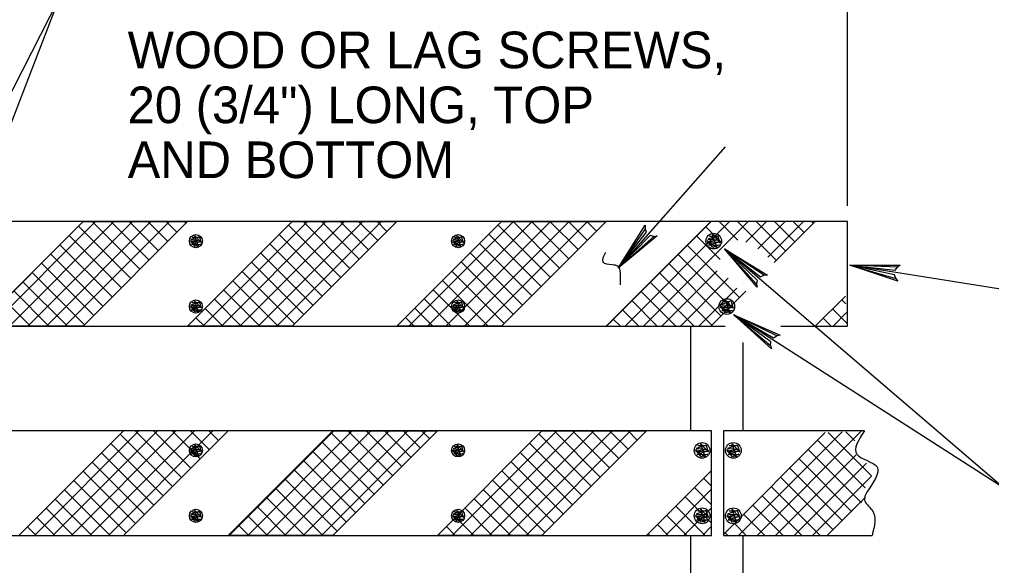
# Model space of a CAD drawing. Extents: x -4 to 901, y -468 to 720.
# Drawn here: x 180 to 269.2, y -1.4 to 48.7 of the extents above; entities that cross this region are included whole.
import ezdxf

# ---------------------------------------------------------------- set-up
doc = ezdxf.new("R2010")
doc.units = 0
doc.layers.add('2', color=7, linetype='Continuous')
doc.layers.add('3', color=7, linetype='Continuous')

msp = doc.modelspace()

# ---------------------------------------------------------------- linework, layer by layer
at = {"layer": '2'}
for p, q in [((255.99775, 41.059875), (255.99775, 66.373875)), ((255.99775, 31.603875), (255.99775, 41.059875)), ((176.23175, 20.563875), (185.83175, 30.163875)), ((185.83175, 20.563875), (195.43175, 30.163875)), ((195.43175, 20.563875), (205.03175, 30.163875)), ((205.03175, 20.563875), (214.63175, 30.163875)), ((214.63175, 20.563875), (224.23175, 30.163875)), ((224.23175, 20.563875), (233.83175, 30.163875)), ((233.83175, 20.563875), (243.43175, 30.163875)), ((249.2665, 26.398625), (253.03175, 30.163875)), ((196.41975, 28.735875), (195.72975, 28.501875)), ((195.85575, 28.735875), (196.41975, 28.735875)), ((196.43175, 27.877875), (196.08975, 28.861875)), ((196.08975, 28.861875), (196.68975, 28.219875)), ((196.68975, 28.219875), (196.50975, 28.801875)), ((220.48375, 28.735875), (219.79375, 28.501875)), ((219.91975, 28.735875), (220.48375, 28.735875)), ((220.49575, 27.877875), (220.15375, 28.861875)), ((220.15375, 28.861875), (220.75375, 28.219875)), ((220.75375, 28.219875), (220.57375, 28.801875)), ((243.99175, 28.809875), (243.16375, 28.527875)), ((243.31575, 28.809875), (243.99175, 28.809875)), ((244.00575, 27.779875), (243.59575, 28.959875)), ((243.59575, 28.959875), (244.31575, 28.189875)), ((244.31575, 28.189875), (244.09975, 28.887875)), ((196.57575, 28.453875), (195.68775, 28.285875)), ((196.11375, 27.877875), (195.68775, 28.423875)), ((195.68775, 28.423875), (196.43175, 27.877875)), ((195.68775, 28.285875), (196.67775, 28.321875)), ((195.72975, 28.501875), (196.57575, 28.453875)), ((196.67775, 28.321875), (195.79575, 28.051875)), ((195.79575, 28.051875), (196.61175, 28.069875)), ((196.61175, 28.069875), (196.11375, 27.877875)), ((196.18575, 28.363875), (196.18575, 28.363875)), ((220.63975, 28.453875), (219.75175, 28.285875)), ((220.17775, 27.877875), (219.75175, 28.423875)), ((219.75175, 28.423875), (220.49575, 27.877875)), ((219.75175, 28.285875), (220.74175, 28.321875)), ((219.79375, 28.501875), (220.63975, 28.453875)), ((220.74175, 28.321875), (219.85975, 28.051875)), ((219.85975, 28.051875), (220.67575, 28.069875)), ((220.67575, 28.069875), (220.17775, 27.877875)), ((220.24975, 28.363875), (220.24975, 28.363875)), ((244.17975, 28.471875), (243.11375, 28.269875)), ((243.62575, 27.779875), (243.11375, 28.435875)), ((243.11375, 28.435875), (244.00575, 27.779875)), ((243.11375, 28.269875), (244.30175, 28.311875)), ((243.16375, 28.527875), (244.17975, 28.471875)), ((244.30175, 28.311875), (243.24375, 27.987875)), ((243.24375, 27.987875), (244.22175, 28.009875)), ((244.22175, 28.009875), (243.62575, 27.779875)), ((243.71175, 28.363875), (243.71175, 28.363875)), ((243.43175, 20.563875), (246.6485, 23.780625)), ((253.03175, 20.563875), (255.79175, 23.323875)), ((196.57575, 22.453875), (195.68775, 22.285875)), ((196.11375, 21.877875), (195.68775, 22.423875)), ((195.68775, 22.423875), (196.43175, 21.877875)), ((195.68775, 22.285875), (196.67775, 22.321875)), ((196.41975, 22.735875), (195.72975, 22.501875)), ((195.72975, 22.501875), (196.57575, 22.453875)), ((196.67775, 22.321875), (195.79575, 22.051875)), ((195.85575, 22.735875), (196.41975, 22.735875)), ((196.43175, 21.877875), (196.08975, 22.861875)), ((196.08975, 22.861875), (196.68975, 22.219875)), ((196.18575, 22.363875), (196.18575, 22.363875)), ((196.68975, 22.219875), (196.50975, 22.801875)), ((220.63975, 22.453875), (219.75175, 22.285875)), ((220.17775, 21.877875), (219.75175, 22.423875)), ((219.75175, 22.423875), (220.49575, 21.877875)), ((219.75175, 22.285875), (220.74175, 22.321875)), ((220.48375, 22.735875), (219.79375, 22.501875)), ((219.79375, 22.501875), (220.63975, 22.453875)), ((220.74175, 22.321875), (219.85975, 22.051875)), ((219.91975, 22.735875), (220.48375, 22.735875)), ((220.49575, 21.877875), (220.15375, 22.861875)), ((220.15375, 22.861875), (220.75375, 22.219875)), ((220.24975, 22.363875), (220.24975, 22.363875)), ((220.75375, 22.219875), (220.57375, 22.801875)), ((245.37975, 22.471875), (244.31375, 22.269875)), ((244.82575, 21.779875), (244.31375, 22.435875)), ((244.31375, 22.435875), (245.20575, 21.779875)), ((244.31375, 22.269875), (245.50175, 22.311875)), ((245.19175, 22.809875), (244.36375, 22.527875)), ((244.36375, 22.527875), (245.37975, 22.471875)), ((245.50175, 22.311875), (244.44375, 21.987875)), ((244.51575, 22.809875), (245.19175, 22.809875)), ((245.20575, 21.779875), (244.79575, 22.959875)), ((244.79575, 22.959875), (245.51575, 22.189875)), ((244.91175, 22.363875), (244.91175, 22.363875)), ((245.51575, 22.189875), (245.29975, 22.887875)), ((195.79575, 22.051875), (196.61175, 22.069875)), ((196.61175, 22.069875), (196.11375, 21.877875)), ((219.85975, 22.051875), (220.67575, 22.069875)), ((220.67575, 22.069875), (220.17775, 21.877875)), ((244.44375, 21.987875), (245.42175, 22.009875)), ((245.42175, 22.009875), (244.82575, 21.779875)), ((241.59775, 10.963875), (241.59775, 20.563875)), ((246.39775, 19.055875), (246.39775, 10.963875)), ((243.5185, 10.963875), (111.99775, 10.963875)), ((179.94575, 1.363875), (189.54575, 10.963875)), ((179.94575, 1.363875), (189.54575, 10.963875)), ((189.54575, 1.363875), (199.14575, 10.963875)), ((189.54575, 1.363875), (199.14575, 10.963875)), ((199.14575, 1.363875), (208.74575, 10.963875)), ((199.14575, 1.363875), (208.74575, 10.963875)), ((208.74575, 1.363875), (218.34575, 10.963875)), ((208.74575, 1.363875), (218.34575, 10.963875)), ((218.34575, 1.363875), (227.94575, 10.963875)), ((218.34575, 1.363875), (227.94575, 10.963875)), ((227.94575, 1.363875), (237.54575, 10.963875)), ((227.94575, 1.363875), (237.54575, 10.963875)), ((243.5185, 1.363875), (243.5185, 10.963875)), ((257.54175, 10.963875), (244.604, 10.963875)), ((244.604, 10.963875), (244.604, 1.363875)), ((244.604, 1.458125), (253.94375, 10.797875)), ((196.57575, 9.253875), (195.68775, 9.085875)), ((196.11375, 8.677875), (195.68775, 9.223875)), ((195.68775, 9.223875), (196.43175, 8.677875)), ((195.68775, 9.085875), (196.67775, 9.121875)), ((196.41975, 9.535875), (195.72975, 9.301875)), ((195.72975, 9.301875), (196.57575, 9.253875)), ((196.67775, 9.121875), (195.79575, 8.851875)), ((195.85575, 9.535875), (196.41975, 9.535875)), ((196.43175, 8.677875), (196.08975, 9.661875)), ((196.08975, 9.661875), (196.68975, 9.019875)), ((196.18575, 9.163875), (196.18575, 9.163875)), ((196.18575, 9.163875), (196.18575, 9.163875)), ((196.68975, 9.019875), (196.50975, 9.601875)), ((220.63975, 9.253875), (219.75175, 9.085875)), ((220.17775, 8.677875), (219.75175, 9.223875)), ((219.75175, 9.223875), (220.49575, 8.677875)), ((219.75175, 9.085875), (220.74175, 9.121875)), ((220.48375, 9.535875), (219.79375, 9.301875)), ((219.79375, 9.301875), (220.63975, 9.253875)), ((220.74175, 9.121875), (219.85975, 8.851875)), ((219.91975, 9.535875), (220.48375, 9.535875)), ((220.49575, 8.677875), (220.15375, 9.661875)), ((220.15375, 9.661875), (220.75375, 9.019875)), ((220.24975, 9.163875), (220.24975, 9.163875)), ((220.24975, 9.163875), (220.24975, 9.163875)), ((220.75375, 9.019875), (220.57375, 9.601875)), ((243.10975, 9.271875), (242.04375, 9.069875)), ((242.55575, 8.579875), (242.04375, 9.235875)), ((242.04375, 9.235875), (242.93775, 8.579875)), ((242.04375, 9.069875), (243.23175, 9.111875)), ((242.92175, 9.609875), (242.09375, 9.327875)), ((242.09375, 9.327875), (243.10975, 9.271875)), ((243.23175, 9.111875), (242.17375, 8.787875)), ((242.24575, 9.609875), (242.92175, 9.609875)), ((242.93775, 8.579875), (242.52575, 9.759875)), ((242.52575, 9.759875), (243.24575, 8.989875)), ((242.64175, 9.163875), (242.64175, 9.163875)), ((242.64175, 9.163875), (242.64175, 9.163875)), ((243.24575, 8.989875), (243.02975, 9.687875)), ((243.11175, 9.163875), (243.11175, 9.163875)), ((245.97975, 9.271875), (244.91375, 9.069875)), ((245.42575, 8.579875), (244.91375, 9.235875)), ((244.91375, 9.235875), (245.80575, 8.579875)), ((244.91375, 9.069875), (246.10175, 9.111875)), ((245.79175, 9.609875), (244.96375, 9.327875)), ((244.96375, 9.327875), (245.97975, 9.271875)), ((246.10175, 9.111875), (245.04375, 8.787875)), ((245.11575, 9.609875), (245.79175, 9.609875)), ((245.80575, 8.579875), (245.39575, 9.759875)), ((245.39575, 9.759875), (246.11575, 8.989875)), ((245.51175, 9.163875), (245.51175, 9.163875)), ((245.51175, 9.163875), (245.51175, 9.163875)), ((246.11575, 8.989875), (245.89975, 9.687875)), ((195.79575, 8.851875), (196.61175, 8.869875)), ((196.61175, 8.869875), (196.11375, 8.677875)), ((219.85975, 8.851875), (220.67575, 8.869875)), ((220.67575, 8.869875), (220.17775, 8.677875)), ((242.17375, 8.787875), (243.15375, 8.809875)), ((243.15375, 8.809875), (242.55575, 8.579875)), ((245.04375, 8.787875), (246.02175, 8.809875)), ((246.02175, 8.809875), (245.42575, 8.579875)), ((237.54575, 1.363875), (243.5185, 7.336625)), ((237.54575, 1.363875), (243.5185, 7.336625)), ((254.10975, 1.363875), (257.62775, 4.881875)), ((196.43175, 2.677875), (196.08975, 3.661875)), ((196.08975, 3.661875), (196.68975, 3.019875)), ((196.68975, 3.019875), (196.50975, 3.601875)), ((220.49575, 2.677875), (220.15375, 3.661875)), ((220.15375, 3.661875), (220.75375, 3.019875)), ((220.75375, 3.019875), (220.57375, 3.601875)), ((242.92175, 3.609875), (242.09375, 3.327875)), ((242.24575, 3.609875), (242.92175, 3.609875)), ((242.93775, 2.579875), (242.52575, 3.759875)), ((242.52575, 3.759875), (243.24575, 2.989875)), ((243.24575, 2.989875), (243.02975, 3.687875)), ((245.79175, 3.609875), (244.96375, 3.327875)), ((245.11575, 3.609875), (245.79175, 3.609875)), ((245.80575, 2.579875), (245.39575, 3.759875)), ((245.39575, 3.759875), (246.11575, 2.989875)), ((246.11575, 2.989875), (245.89975, 3.687875)), ((196.57575, 3.253875), (195.68775, 3.085875)), ((196.11375, 2.677875), (195.68775, 3.223875)), ((195.68775, 3.223875), (196.43175, 2.677875)), ((195.68775, 3.085875), (196.67775, 3.121875)), ((196.41975, 3.535875), (195.72975, 3.301875)), ((195.72975, 3.301875), (196.57575, 3.253875)), ((196.67775, 3.121875), (195.79575, 2.851875)), ((195.79575, 2.851875), (196.61175, 2.869875)), ((195.85575, 3.535875), (196.41975, 3.535875)), ((196.61175, 2.869875), (196.11375, 2.677875)), ((196.18575, 3.163875), (196.18575, 3.163875)), ((196.18575, 3.163875), (196.18575, 3.163875)), ((220.63975, 3.253875), (219.75175, 3.085875)), ((220.17775, 2.677875), (219.75175, 3.223875)), ((219.75175, 3.223875), (220.49575, 2.677875)), ((219.75175, 3.085875), (220.74175, 3.121875)), ((220.48375, 3.535875), (219.79375, 3.301875)), ((219.79375, 3.301875), (220.63975, 3.253875)), ((220.74175, 3.121875), (219.85975, 2.851875)), ((219.85975, 2.851875), (220.67575, 2.869875)), ((219.91975, 3.535875), (220.48375, 3.535875)), ((220.67575, 2.869875), (220.17775, 2.677875)), ((220.24975, 3.163875), (220.24975, 3.163875)), ((220.24975, 3.163875), (220.24975, 3.163875)), ((243.10975, 3.271875), (242.04375, 3.069875)), ((242.55575, 2.579875), (242.04375, 3.235875)), ((242.04375, 3.235875), (242.93775, 2.579875)), ((242.04375, 3.069875), (243.23175, 3.111875)), ((242.09375, 3.327875), (243.10975, 3.271875)), ((243.23175, 3.111875), (242.17375, 2.787875)), ((242.17375, 2.787875), (243.15375, 2.809875)), ((243.15375, 2.809875), (242.55575, 2.579875)), ((242.64175, 3.163875), (242.64175, 3.163875)), ((242.64175, 3.163875), (242.64175, 3.163875)), ((245.97975, 3.271875), (244.91375, 3.069875)), ((245.42575, 2.579875), (244.91375, 3.235875)), ((244.91375, 3.235875), (245.80575, 2.579875)), ((244.91375, 3.069875), (246.10175, 3.111875)), ((244.96375, 3.327875), (245.97975, 3.271875)), ((246.10175, 3.111875), (245.04375, 2.787875)), ((245.04375, 2.787875), (246.02175, 2.809875)), ((246.02175, 2.809875), (245.42575, 2.579875)), ((245.51175, 3.163875), (245.51175, 3.163875)), ((111.99775, 1.363875), (243.5185, 1.363875)), ((244.604, 1.363875), (258.23975, 1.363875))]:
    msp.add_line(p, q, dxfattribs=at)
for points in [[(188.42975, 50.693875), (183.62975, 50.693875), (172.57375, 28.971875)], [(183.62975, 50.693875), (172.72375, 22.369875)], [(244.757, 37.016375), (234.93175, 25.897875)], [(170.943, 30.163875), (111.99775, 30.163875), (111.99775, 20.563875), (244.7635, 20.563875)], [(249.87225, 20.563875), (255.99775, 20.563875), (255.99775, 30.163875), (174.7745, 30.163875)], [(177.37375, 20.563875), (186.97375, 30.161875)], [(179.07175, 20.563875), (188.66975, 30.163875)], [(180.76775, 20.563875), (190.36775, 30.163875)], [(182.46575, 20.563875), (192.06375, 30.163875)], [(184.16175, 20.563875), (193.76175, 30.163875)], [(190.20375, 24.935875), (185.40375, 29.735875)], [(191.05175, 25.783875), (186.67375, 30.163875)], [(191.89975, 26.631875), (188.36975, 30.163875)], [(192.74975, 27.481875), (190.06775, 30.163875)], [(193.59775, 28.329875), (191.76375, 30.163875)], [(194.44575, 29.177875), (193.46175, 30.163875)], [(195.29375, 30.025875), (195.15775, 30.163875)], [(196.82375, 20.563875), (206.42375, 30.163875)], [(198.52175, 20.563875), (208.12175, 30.163875)], [(200.21775, 20.563875), (209.81775, 30.163875)], [(201.91575, 20.563875), (211.51575, 30.163875)], [(203.61175, 20.563875), (213.21175, 30.163875)], [(209.48175, 25.013875), (204.68175, 29.813875)], [(210.32975, 25.861875), (206.02975, 30.163875)], [(211.17975, 26.709875), (207.72775, 30.163875)], [(212.02775, 27.559875), (209.42375, 30.163875)], [(212.87575, 28.407875), (211.12175, 30.163875)], [(213.72375, 29.255875), (212.81775, 30.163875)], [(214.57375, 30.103875), (214.51575, 30.163875)], [(215.74375, 20.563875), (225.34375, 30.163875)], [(217.44175, 20.563875), (227.04175, 30.163875)], [(219.13775, 20.563875), (228.73775, 30.163875)], [(220.83575, 20.563875), (230.43575, 30.163875)], [(222.53175, 20.563875), (232.13175, 30.163875)], [(228.71175, 25.043875), (223.91175, 29.843875)], [(224.22975, 20.563875), (233.82975, 30.163875)], [(229.56175, 25.893875), (225.29175, 30.163875)], [(230.40975, 26.741875), (226.98775, 30.163875)], [(231.25775, 27.589875), (228.68575, 30.163875)], [(232.10775, 28.437875), (230.38175, 30.163875)], [(232.95575, 29.287875), (232.07975, 30.163875)], [(233.80375, 30.135875), (233.77575, 30.163875)], [(233.87175, 20.563875), (243.47175, 30.163875)], [(238.22975, 28.801875), (237.88575, 28.889875), (234.93175, 25.897875), (238.22975, 28.801875), (238.51975, 28.841875), (234.93175, 25.897875), (237.55375, 29.177875), (237.42175, 29.497875), (234.93175, 25.897875), (237.42175, 29.813875), (237.42175, 29.497875)], [(235.56975, 20.563875), (245.16775, 30.163875)], [(237.26575, 20.563875), (246.86575, 30.163875)], [(244.426, 28.249625), (242.97175, 29.703875)], [(245.91325, 28.459625), (244.20975, 30.163875)], [(249.46775, 26.599875), (245.90575, 30.163875)], [(246.6725, 28.274375), (248.56175, 30.163875)], [(250.31775, 27.449875), (247.60375, 30.161875)], [(247.761, 27.665125), (250.25975, 30.163875)], [(248.6735, 26.879625), (251.95775, 30.163875)], [(251.16575, 28.297875), (249.29975, 30.163875)], [(252.01375, 29.145875), (250.99775, 30.163875)], [(252.86175, 29.993875), (252.69375, 30.163875)], [(189.35575, 24.085875), (184.55575, 28.885875)], [(208.63375, 24.165875), (203.83375, 28.965875)], [(227.86375, 24.195875), (223.06375, 28.995875)], [(244.312, 26.666625), (242.12375, 28.853875)], [(188.50575, 23.237875), (183.70575, 28.037875)], [(207.78575, 23.315875), (202.98575, 28.115875)], [(227.01575, 23.347875), (222.21575, 28.147875)], [(246.07375, 23.205875), (241.27375, 28.005875)], [(275.09575, 5.731875), (270.29575, 5.731875), (244.68575, 27.669875)], [(247.63975, 24.417875), (247.72175, 24.763875), (244.68575, 27.669875), (247.63975, 24.417875), (247.68575, 24.127875), (244.68575, 27.669875), (248.00575, 25.097875), (248.32575, 25.235875), (244.68575, 27.669875), (248.63975, 25.239875), (248.32575, 25.235875)], [(187.65775, 22.389875), (182.85775, 27.189875)], [(206.93575, 22.467875), (202.13575, 27.267875)], [(226.16775, 22.499875), (221.36775, 27.299875)], [(245.22575, 22.357875), (240.42575, 27.157875)], [(186.80975, 21.541875), (182.00975, 26.341875)], [(206.08775, 21.619875), (201.28775, 26.419875)], [(225.31775, 21.649875), (220.51775, 26.449875)], [(244.37775, 21.509875), (239.57775, 26.309875)], [(274.65975, 23.975875), (269.85975, 23.975875), (256.19775, 26.147875)], [(260.41775, 24.923875), (260.30575, 25.261875), (256.19775, 26.147875), (260.41775, 24.923875), (260.60775, 24.699875), (256.19775, 26.147875), (260.37175, 25.695875), (260.57175, 25.979875), (256.19775, 26.147875), (260.83775, 26.147875), (260.57175, 25.979875)], [(185.96175, 20.691875), (181.16175, 25.491875)], [(205.23975, 20.771875), (200.43975, 25.571875)], [(224.46975, 20.801875), (219.66975, 25.601875)], [(243.52975, 20.659875), (238.72975, 25.459875)], [(238.96375, 20.563875), (244.02275, 25.623875)], [(184.39375, 20.563875), (180.31175, 24.643875)], [(203.74975, 20.563875), (199.59175, 24.721875)], [(223.01175, 20.563875), (218.82175, 24.753875)], [(241.92975, 20.563875), (237.87975, 24.611875)], [(240.65975, 20.563875), (245.047, 24.951125)], [(182.69575, 20.563875), (179.46375, 23.795875)], [(202.05375, 20.563875), (198.74175, 23.873875)], [(221.31575, 20.563875), (217.97375, 23.905875)], [(240.23175, 20.563875), (237.03175, 23.763875)], [(242.35775, 20.563875), (245.848, 24.054125)], [(180.99975, 20.563875), (178.61575, 22.947875)], [(200.35575, 20.563875), (197.89375, 23.025875)], [(219.61775, 20.563875), (217.12375, 23.055875)], [(238.53575, 20.561875), (236.18375, 22.915875)], [(255.84575, 22.601875), (255.45775, 22.989875)], [(198.65975, 20.563875), (197.04575, 22.177875)], [(217.92175, 20.563875), (216.27575, 22.207875)], [(236.83775, 20.563875), (235.33575, 22.065875)], [(270.29575, 5.731875), (245.55375, 21.587875)], [(248.92975, 18.773875), (248.96375, 19.127875), (245.55375, 21.587875), (248.92975, 18.773875), (249.01375, 18.491875), (245.55375, 21.587875), (249.19775, 19.499875), (249.49375, 19.679875), (245.55375, 21.587875), (249.80575, 19.727875), (249.49375, 19.679875)], [(255.98175, 20.767875), (254.60975, 22.141875)], [(254.66175, 20.563875), (255.90575, 21.805875)], [(196.96175, 20.563875), (196.19575, 21.327875)], [(216.22375, 20.563875), (215.42775, 21.359875)], [(235.14175, 20.563875), (234.48575, 21.217875)], [(254.48975, 20.563875), (253.76175, 21.291875)], [(181.36375, 1.363875), (190.96175, 10.961875)], [(183.05975, 1.363875), (192.65975, 10.963875)], [(184.75775, 1.363875), (194.35775, 10.963875)], [(186.45375, 1.363875), (196.05375, 10.963875)], [(188.15175, 1.363875), (197.75175, 10.963875)], [(194.87375, 6.691875), (190.60175, 10.963875)], [(195.72175, 7.539875), (192.29775, 10.963875)], [(196.56975, 8.387875), (193.99575, 10.963875)], [(197.41975, 9.235875), (195.69175, 10.963875)], [(198.26775, 10.085875), (197.38975, 10.963875)], [(199.11575, 10.933875), (199.08575, 10.963875)], [(199.24175, 1.363875), (208.84175, 10.961875)], [(200.93975, 1.363875), (210.53975, 10.963875)], [(202.63575, 1.363875), (212.23575, 10.963875)], [(204.33375, 1.363875), (213.93375, 10.963875)], [(206.03175, 1.363875), (215.63175, 10.963875)], [(207.72775, 1.363875), (217.32775, 10.963875)], [(213.38375, 5.999875), (208.58375, 10.799875)], [(214.23175, 6.849875), (210.11775, 10.963875)], [(215.07975, 7.697875), (211.81575, 10.963875)], [(215.92775, 8.545875), (213.51175, 10.963875)], [(216.77775, 9.393875), (215.20975, 10.963875)], [(217.62575, 10.243875), (216.90575, 10.963875)], [(219.69975, 1.363875), (229.29975, 10.963875)], [(221.39575, 1.363875), (230.99575, 10.963875)], [(223.09375, 1.363875), (232.69375, 10.963875)], [(224.78975, 1.363875), (234.38975, 10.963875)], [(226.48775, 1.363875), (236.08775, 10.963875)], [(233.30375, 6.721875), (229.06375, 10.963875)], [(234.15375, 7.569875), (230.76175, 10.963875)], [(235.00175, 8.419875), (232.45775, 10.963875)], [(235.84975, 9.267875), (234.15575, 10.963875)], [(236.69775, 10.115875), (235.85175, 10.963875)], [(245.98775, 1.363875), (255.49375, 10.867875)], [(247.68575, 1.363875), (257.27175, 10.949875)], [(258.20175, 6.827875), (254.21975, 10.809875)], [(256.67175, 10.055875), (255.84375, 10.883875)], [(257.50375, 10.921875), (257.46575, 10.959875)], [(194.02575, 5.841875), (189.22575, 10.641875)], [(212.53375, 5.151875), (207.73375, 9.951875)], [(231.60775, 5.025875), (226.80775, 9.825875)], [(232.45575, 5.873875), (227.65575, 10.673875)], [(257.60575, 5.727875), (253.23975, 10.093875)], [(192.32775, 4.145875), (187.52775, 8.945875)], [(193.17575, 4.993875), (188.37575, 9.793875)], [(211.68575, 4.303875), (206.88575, 9.103875)], [(230.75975, 4.175875), (225.95975, 8.975875)], [(257.26775, 4.367875), (252.39175, 9.245875)], [(191.47975, 3.295875), (186.67975, 8.095875)], [(210.83775, 3.455875), (206.03775, 8.255875)], [(229.90975, 3.327875), (225.10975, 8.127875)], [(249.38175, 1.363875), (256.77975, 8.761875)], [(256.39975, 3.539875), (251.54175, 8.395875)], [(190.62975, 2.447875), (185.82975, 7.247875)], [(209.98975, 2.605875), (205.18975, 7.405875)], [(229.06175, 2.479875), (224.26175, 7.279875)], [(255.53175, 2.711875), (250.69375, 7.547875)], [(251.07975, 1.363875), (257.72175, 8.005875)], [(189.78175, 1.599875), (184.98175, 6.399875)], [(209.13975, 1.757875), (204.33975, 6.557875)], [(228.21375, 1.631875), (223.41375, 6.431875)], [(243.5185, 5.871125), (242.78575, 6.603875)], [(254.66175, 1.881875), (249.84575, 6.699875)], [(252.77575, 1.363875), (258.20175, 6.789875)], [(188.32175, 1.363875), (184.13375, 5.551875)], [(207.83775, 1.363875), (203.49175, 5.709875)], [(226.78375, 1.363875), (222.56575, 5.581875)], [(239.27775, 1.363875), (243.5185, 5.604625)], [(243.5185, 4.175125), (241.93775, 5.755875)], [(253.48375, 1.363875), (248.99775, 5.851875)], [(186.62575, 1.363875), (183.28575, 4.701875)], [(206.14175, 1.363875), (202.64375, 4.861875)], [(225.08775, 1.363875), (221.71575, 4.733875)], [(243.5185, 2.477375), (241.08975, 4.907875)], [(251.78775, 1.363875), (248.14775, 5.001875)], [(184.92775, 1.363875), (182.43575, 3.853875)], [(204.44375, 1.363875), (201.79575, 4.011875)], [(223.38975, 1.363875), (220.86775, 3.885875)], [(242.93575, 1.363875), (240.24175, 4.057875)], [(240.97375, 1.363875), (243.5185, 3.908625)], [(250.08975, 1.363875), (247.29975, 4.153875)], [(183.23175, 1.363875), (181.58775, 3.005875)], [(202.74775, 1.363875), (200.94575, 3.163875)], [(221.69375, 1.363875), (220.01975, 3.037875)], [(241.23975, 1.363875), (239.39175, 3.209875)], [(248.39375, 1.363875), (246.45175, 3.305875)], [(181.53375, 1.363875), (180.73975, 2.157875)], [(201.04975, 1.363875), (200.09775, 2.315875)], [(219.99575, 1.363875), (219.17175, 2.187875)], [(239.54175, 1.363875), (238.54375, 2.361875)], [(242.67175, 1.363875), (243.5185, 2.210625)], [(246.69575, 1.363875), (245.60375, 2.455875)], [(199.35375, 1.363875), (199.24975, 1.465875)], [(237.84575, 1.363875), (237.69575, 1.513875)], [(241.59775, -8.236125), (241.59775, 1.363875)], [(244.999, 1.363875), (244.75375, 1.607875)], [(246.39775, 1.363875), (246.39775, -8.236125)]]:
    msp.add_lwpolyline(points, dxfattribs=at)
for points in [[(176.23175, 20.563875), (185.83175, 30.163875), (195.43175, 30.163875), (185.83175, 20.563875)], [(195.43175, 20.563875), (205.03175, 30.163875), (214.63175, 30.163875), (205.03175, 20.563875)], [(214.63175, 20.563875), (224.23175, 30.163875), (233.83175, 30.163875), (224.23175, 20.563875)], [(199.14575, 1.363875), (208.74575, 10.963875), (218.34575, 10.963875), (208.74575, 1.363875)], [(218.34575, 1.363875), (227.94575, 10.963875), (237.54575, 10.963875), (227.94575, 1.363875)]]:
    msp.add_lwpolyline(points, close=True, dxfattribs=at)
for centre, radius in [((196.18605, 28.362972), 0.6), ((220.24893, 28.362972), 0.6), ((243.71157, 28.362972), 0.72), ((196.18605, 22.362972), 0.6), ((220.24893, 22.362972), 0.6), ((244.91157, 22.362972), 0.72), ((242.64189, 9.162972), 0.72), ((245.51157, 9.162972), 0.72), ((196.18605, 9.162972), 0.6), ((220.24893, 9.162972), 0.6), ((196.18605, 3.162972), 0.6), ((220.24893, 3.162972), 0.6), ((242.64189, 3.162972), 0.72), ((245.51157, 3.162972), 0.72)]:
    msp.add_circle(centre, radius, dxfattribs=at)
for points in [[(233.77975, 27.315875), (233.53375, 26.453875), (234.39375, 26.209875), (234.88575, 26.085875), (235.13175, 25.101875), (235.13175, 24.363875)], [(257.54175, 10.963875), (256.84575, 8.807875), (258.70375, 7.645875), (257.77575, 5.325875), (257.54175, 4.627875), (258.23975, 3.699875), (258.23975, 1.363875)], [(257.54175, 10.963875), (256.84575, 8.807875), (258.70375, 7.645875), (257.77575, 5.325875), (257.54175, 4.627875), (258.23975, 3.699875), (258.23975, 1.363875)]]:
    msp.add_spline(points, degree=3, dxfattribs=at)

# ---------------------------------------------------------------- texts
at = {"layer": '3'}
for s, p in [('WOOD OR LAG SCREWS,', (189.92375, 44.223875)), ('20 (3/4") LONG, TOP', (189.92375, 39.183875)), ('AND BOTTOM', (189.92375, 34.143875))]:
    msp.add_text(s, height=3.359988, dxfattribs=at).set_placement(p)

doc.saveas('drawing.dxf')
